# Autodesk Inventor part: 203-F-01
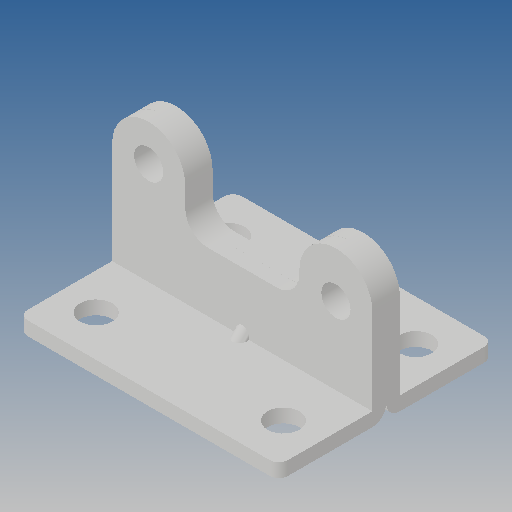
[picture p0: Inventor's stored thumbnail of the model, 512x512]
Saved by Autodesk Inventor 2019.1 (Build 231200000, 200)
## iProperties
Created: 2012-09
Part Number: 203-F-01
Material: Ogólny
Document SubType Name: Modeling
Designer: CADENGINEERING4
Density: 1 g/cm^3
Appearance: Domyślna
Author: CADENGINEERING4
Revision Number: ÈÎºÎ
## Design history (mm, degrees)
feature "µ¹½Ç2"
feature "¾µÏò4"
node "Bryła1"
node "Bryła2"
